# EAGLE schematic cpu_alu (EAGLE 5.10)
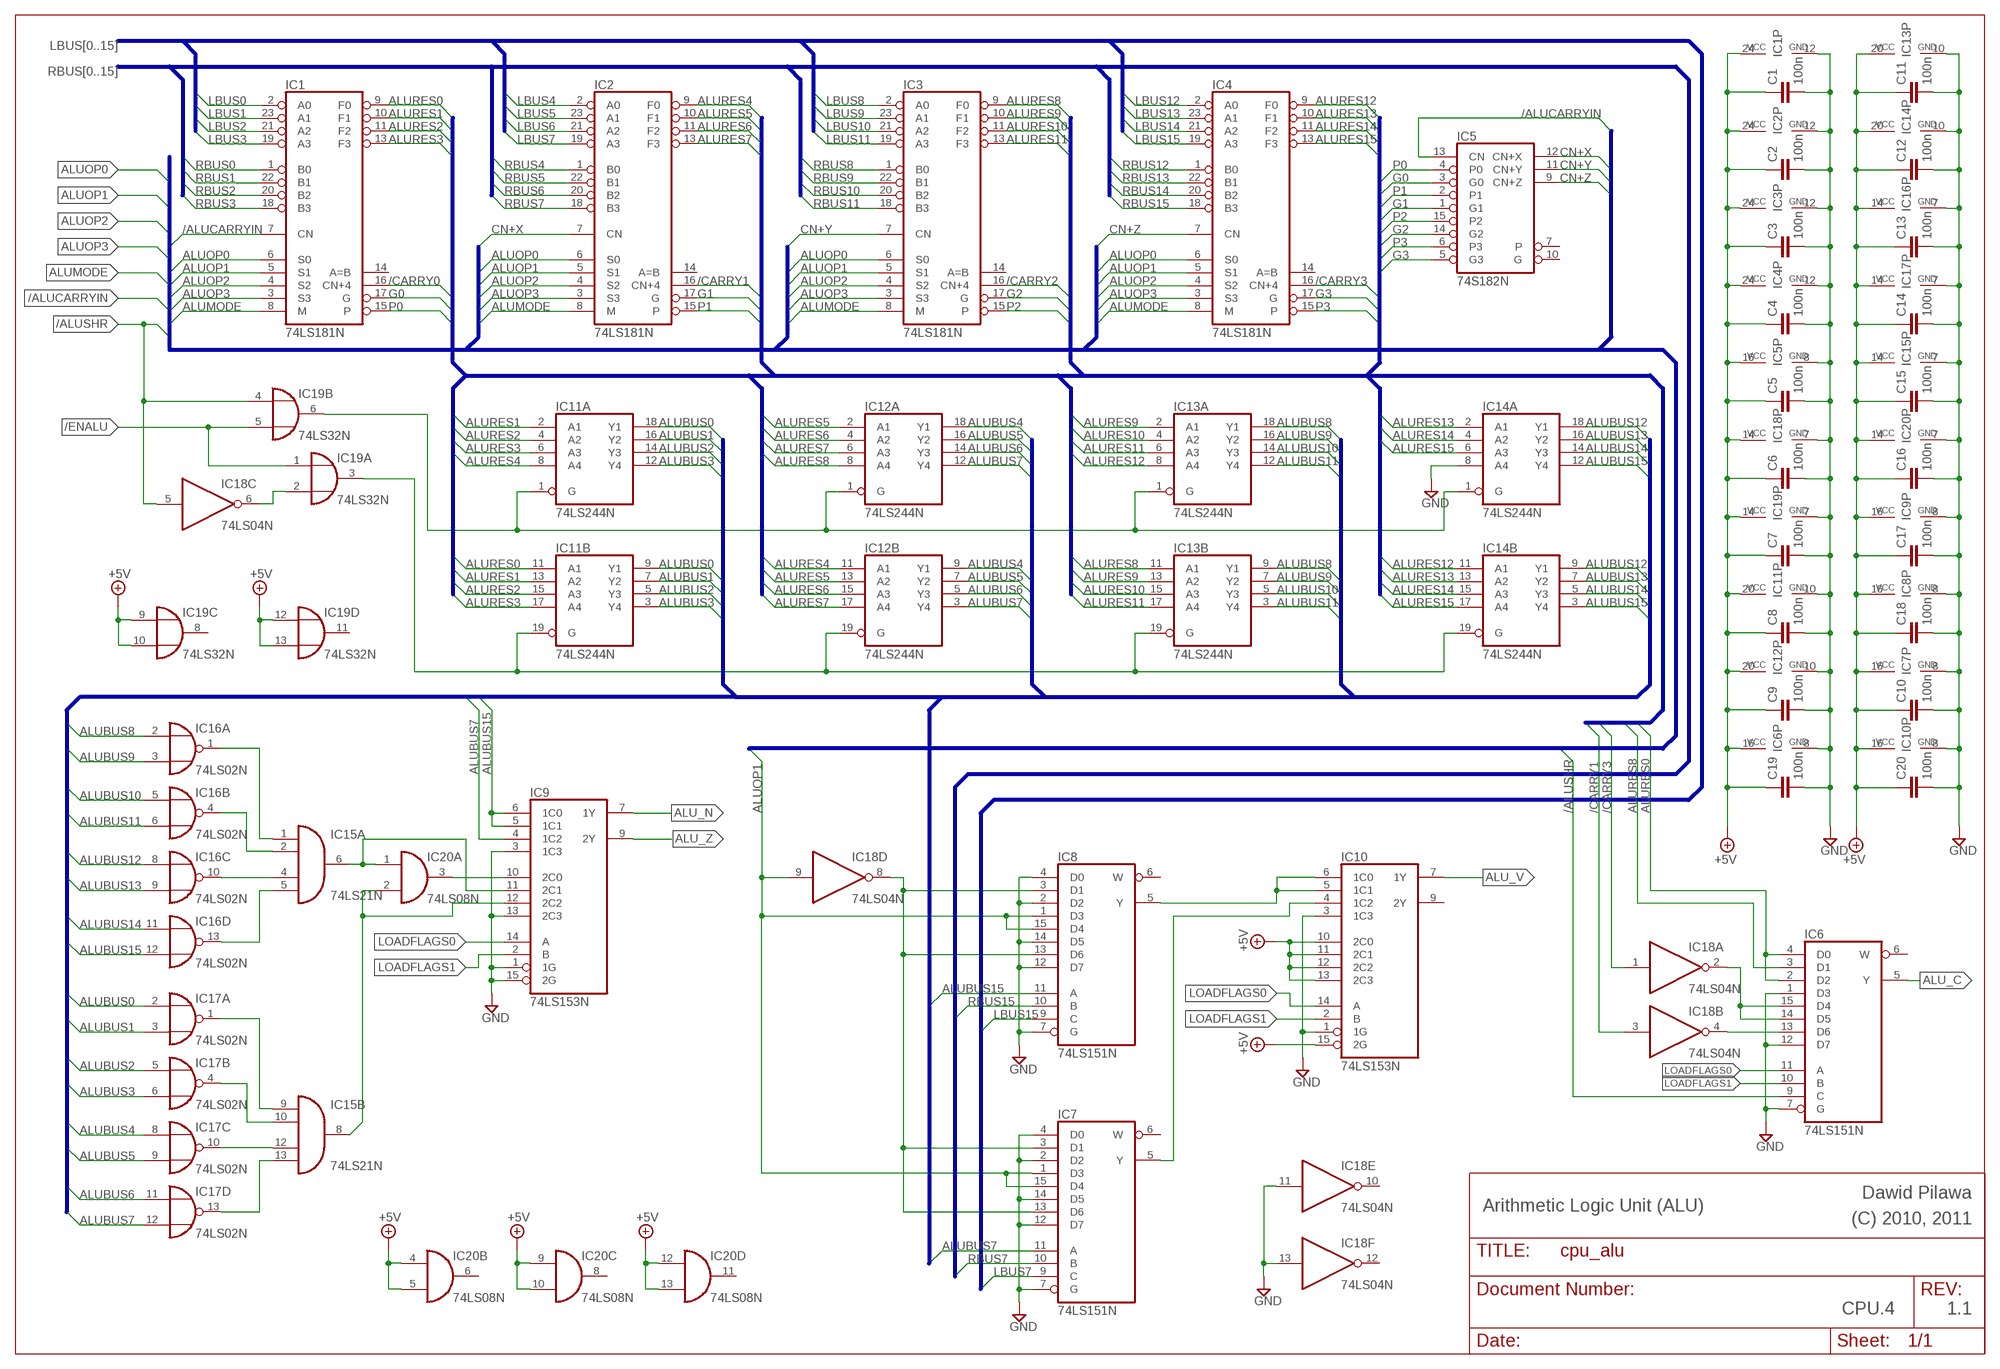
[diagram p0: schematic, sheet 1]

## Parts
C1  100n  C-EU050-024X044  [C050-024X044]
C2  100n  C-EU050-024X044  [C050-024X044]
C3  100n  C-EU050-024X044  [C050-024X044]
C4  100n  C-EU050-024X044  [C050-024X044]
C5  100n  C-EU050-024X044  [C050-024X044]
C6  100n  C-EU050-024X044  [C050-024X044]
C7  100n  C-EU050-024X044  [C050-024X044]
C8  100n  C-EU050-024X044  [C050-024X044]
C9  100n  C-EU050-024X044  [C050-024X044]
C10  100n  C-EU050-024X044  [C050-024X044]
C11  100n  C-EU050-024X044  [C050-024X044]
C12  100n  C-EU050-024X044  [C050-024X044]
C13  100n  C-EU050-024X044  [C050-024X044]
C14  100n  C-EU050-024X044  [C050-024X044]
C15  100n  C-EU050-024X044  [C050-024X044]
C16  100n  C-EU050-024X044  [C050-024X044]
C17  100n  C-EU050-024X044  [C050-024X044]
C18  100n  C-EU050-024X044  [C050-024X044]
C19  100n  C-EU050-024X044  [C050-024X044]
C20  100n  C-EU050-024X044  [C050-024X044]
IC1  74LS181N  [DIL24-6]
IC2  74LS181N  [DIL24-6]
IC3  74LS181N  [DIL24-6]
IC4  74LS181N  [DIL24-6]
IC5  74S182N  [DIL16]
IC6  74LS151N  [DIL16]
IC7  74LS151N  [DIL16]
IC8  74LS151N  [DIL16]
IC9  74LS153N  [DIL16]
IC10  74LS153N  [DIL16]
IC11  74LS244N  [DIL20]
IC12  74LS244N  [DIL20]
IC13  74LS244N  [DIL20]
IC14  74LS244N  [DIL20]
IC15  74LS21N  [DIL14]
IC16  74LS02N  [DIL14]
IC17  74LS02N  [DIL14]
IC18  74LS04N  [DIL14]
IC19  74LS32N  [DIL14]
IC20  74LS08N  [DIL14]

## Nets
+5V: C1.1 C2.1 C3.1 C4.1 C5.1 C6.1 C7.1 C8.1 C9.1 C10.1 C11.1 C12.1 C13.1 C14.1 C15.1 C16.1 C17.1 C18.1 C19.1 C20.1 IC1.24(VCC) IC2.24(VCC) IC3.24(VCC) IC4.24(VCC) IC5.16(VCC) IC6.16(VCC) IC7.16(VCC) IC8.16(VCC) IC9.16(VCC) IC10.10(2C0) IC10.11(2C1) IC10.12(2C2) IC10.13(2C3) IC10.15(2G) IC10.16(VCC) IC11.20(P:VCC) IC12.20(P:VCC) IC13.20(P:VCC) IC14.20(P:VCC) IC15.14(P:VCC) IC16.14(P:VCC) IC17.14(P:VCC) IC18.14(P:VCC) IC19.9(C:I0) IC19.10(C:I1) IC19.12(D:I0) IC19.13(D:I1) IC19.14(P:VCC) IC20.4(B:I0) IC20.5(B:I1) IC20.9(C:I0) IC20.10(C:I1) IC20.12(D:I0) IC20.13(D:I1) IC20.14(P:VCC)
/ALUCARRYIN: IC1.7(CN) IC5.13(CN)
/ALUSHR: IC6.9(C) IC18.5(C:I) IC19.4(B:I0)
/CARRY0: IC1.16(CN+4)
/CARRY1: IC2.16(CN+4) IC18.3(B:I)
/CARRY2: IC3.16(CN+4)
/CARRY3: IC4.16(CN+4) IC18.1(A:I)
/ENALU: IC19.1(A:I0) IC19.5(B:I1)
ALU_C: IC6.5(Y)
ALU_N: IC9.7(1Y)
ALU_V: IC10.7(1Y)
ALU_Z: IC9.9(2Y)
ALUBUS0: IC11.9(B:Y1) IC11.18(A:Y1) IC17.2(A:I0)
ALUBUS1: IC11.7(B:Y2) IC11.16(A:Y2) IC17.3(A:I1)
ALUBUS2: IC11.5(B:Y3) IC11.14(A:Y3) IC17.5(B:I0)
ALUBUS3: IC11.3(B:Y4) IC11.12(A:Y4) IC17.6(B:I1)
ALUBUS4: IC12.9(B:Y1) IC12.18(A:Y1) IC17.8(C:I0)
ALUBUS5: IC12.7(B:Y2) IC12.16(A:Y2) IC17.9(C:I1)
ALUBUS6: IC12.5(B:Y3) IC12.14(A:Y3) IC17.11(D:I0)
ALUBUS7: IC7.11(A) IC9.4(1C2) IC12.3(B:Y4) IC12.12(A:Y4) IC17.12(D:I1)
ALUBUS8: IC13.9(B:Y1) IC13.18(A:Y1) IC16.2(A:I0)
ALUBUS9: IC13.7(B:Y2) IC13.16(A:Y2) IC16.3(A:I1)
ALUBUS10: IC13.5(B:Y3) IC13.14(A:Y3) IC16.5(B:I0)
ALUBUS11: IC13.3(B:Y4) IC13.12(A:Y4) IC16.6(B:I1)
ALUBUS12: IC14.9(B:Y1) IC14.18(A:Y1) IC16.8(C:I0)
ALUBUS13: IC14.7(B:Y2) IC14.16(A:Y2) IC16.9(C:I1)
ALUBUS14: IC14.5(B:Y3) IC14.14(A:Y3) IC16.11(D:I0)
ALUBUS15: IC8.11(A) IC9.5(1C1) IC9.6(1C0) IC14.3(B:Y4) IC14.12(A:Y4) IC16.12(D:I1)
ALUMODE: IC1.8(M) IC2.8(M) IC3.8(M) IC4.8(M)
ALUOP0: IC1.6(S0) IC2.6(S0) IC3.6(S0) IC4.6(S0)
ALUOP1: IC1.5(S1) IC2.5(S1) IC3.5(S1) IC4.5(S1) IC7.1(D3) IC7.15(D4) IC8.1(D3) IC8.15(D4) IC18.9(D:I)
ALUOP2: IC1.4(S2) IC2.4(S2) IC3.4(S2) IC4.4(S2)
ALUOP3: IC1.3(S3) IC2.3(S3) IC3.3(S3) IC4.3(S3)
ALURES0: IC1.9(F0) IC6.2(D2) IC6.4(D0) IC11.11(B:A1)
ALURES1: IC1.10(F1) IC11.2(A:A1) IC11.13(B:A2)
ALURES2: IC1.11(F2) IC11.4(A:A2) IC11.15(B:A3)
ALURES3: IC1.13(F3) IC11.6(A:A3) IC11.17(B:A4)
ALURES4: IC2.9(F0) IC11.8(A:A4) IC12.11(B:A1)
ALURES5: IC2.10(F1) IC12.2(A:A1) IC12.13(B:A2)
ALURES6: IC2.11(F2) IC12.4(A:A2) IC12.15(B:A3)
ALURES7: IC2.13(F3) IC12.6(A:A3) IC12.17(B:A4)
ALURES8: IC3.9(F0) IC6.3(D1) IC12.8(A:A4) IC13.11(B:A1)
ALURES9: IC3.10(F1) IC13.2(A:A1) IC13.13(B:A2)
ALURES10: IC3.11(F2) IC13.4(A:A2) IC13.15(B:A3)
ALURES11: IC3.13(F3) IC13.6(A:A3) IC13.17(B:A4)
ALURES12: IC4.9(F0) IC13.8(A:A4) IC14.11(B:A1)
ALURES13: IC4.10(F1) IC14.2(A:A1) IC14.13(B:A2)
ALURES14: IC4.11(F2) IC14.4(A:A2) IC14.15(B:A3)
ALURES15: IC4.13(F3) IC14.6(A:A3) IC14.17(B:A4)
CN+X: IC2.7(CN) IC5.12(CN+X)
CN+Y: IC3.7(CN) IC5.11(CN+Y)
CN+Z: IC4.7(CN) IC5.9(CN+Z)
G0: IC1.17(G) IC5.3(G0)
G1: IC2.17(G) IC5.1(G1)
G2: IC3.17(G) IC5.14(G2)
G3: IC4.17(G) IC5.5(G3)
GND: C1.2 C2.2 C3.2 C4.2 C5.2 C6.2 C7.2 C8.2 C9.2 C10.2 C11.2 C12.2 C13.2 C14.2 C15.2 C16.2 C17.2 C18.2 C19.2 C20.2 IC1.12(GND) IC2.12(GND) IC3.12(GND) IC4.12(GND) IC5.8(GND) IC6.1(D3) IC6.7(G) IC6.8(GND) IC6.12(D7) IC7.2(D2) IC7.4(D0) IC7.7(G) IC7.8(GND) IC7.12(D7) IC7.14(D5) IC8.2(D2) IC8.4(D0) IC8.7(G) IC8.8(GND) IC8.12(D7) IC8.14(D5) IC9.1(1G) IC9.3(1C3) IC9.8(GND) IC9.13(2C3) IC9.15(2G) IC10.1(1G) IC10.3(1C3) IC10.8(GND) IC11.10(P:GND) IC12.10(P:GND) IC13.10(P:GND) IC14.8(A:A4) IC14.10(P:GND) IC15.7(P:GND) IC16.7(P:GND) IC17.7(P:GND) IC18.7(P:GND) IC18.11(E:I) IC18.13(F:I) IC19.7(P:GND) IC20.7(P:GND)
LBUS0: IC1.2(A0)
LBUS1: IC1.23(A1)
LBUS2: IC1.21(A2)
LBUS3: IC1.19(A3)
LBUS4: IC2.2(A0)
LBUS5: IC2.23(A1)
LBUS6: IC2.21(A2)
LBUS7: IC2.19(A3) IC7.9(C)
LBUS8: IC3.2(A0)
LBUS9: IC3.23(A1)
LBUS10: IC3.21(A2)
LBUS11: IC3.19(A3)
LBUS12: IC4.2(A0)
LBUS13: IC4.23(A1)
LBUS14: IC4.21(A2)
LBUS15: IC4.19(A3) IC8.9(C)
LOADFLAGS0: IC6.11(A) IC9.14(A) IC10.14(A)
LOADFLAGS1: IC6.10(B) IC9.2(B) IC10.2(B)
N$1: IC11.1(A:G) IC12.1(A:G) IC13.1(A:G) IC14.1(A:G) IC19.6(B:O)
N$2: IC6.13(D6) IC18.4(B:O)
N$3: IC6.14(D5) IC6.15(D4) IC18.2(A:O)
N$4: IC18.6(C:O) IC19.2(A:I1)
N$5: IC11.19(B:G) IC12.19(B:G) IC13.19(B:G) IC14.19(B:G) IC19.3(A:O)
N$6: IC15.1(A:I0) IC16.1(A:O)
N$7: IC15.2(A:I1) IC16.4(B:O)
N$8: IC15.4(A:I2) IC16.10(C:O)
N$9: IC15.5(A:I3) IC16.13(D:O)
N$10: IC15.9(B:I0) IC17.1(A:O)
N$11: IC15.10(B:I1) IC17.4(B:O)
N$12: IC15.12(B:I2) IC17.10(C:O)
N$13: IC15.13(B:I3) IC17.13(D:O)
N$14: IC9.11(2C1) IC15.6(A:O) IC20.1(A:I0)
N$15: IC9.12(2C2) IC15.8(B:O) IC20.2(A:I1)
N$16: IC9.10(2C0) IC20.3(A:O)
N$17: IC8.5(Y) IC10.5(1C1) IC10.6(1C0)
N$19: IC7.5(Y) IC10.4(1C2)
N$21: IC7.3(D1) IC7.13(D6) IC8.3(D1) IC8.13(D6) IC18.8(D:O)
P0: IC1.15(P) IC5.4(P0)
P1: IC2.15(P) IC5.2(P1)
P2: IC3.15(P) IC5.15(P2)
P3: IC4.15(P) IC5.6(P3)
RBUS0: IC1.1(B0)
RBUS1: IC1.22(B1)
RBUS2: IC1.20(B2)
RBUS3: IC1.18(B3)
RBUS4: IC2.1(B0)
RBUS5: IC2.22(B1)
RBUS6: IC2.20(B2)
RBUS7: IC2.18(B3) IC7.10(B)
RBUS8: IC3.1(B0)
RBUS9: IC3.22(B1)
RBUS10: IC3.20(B2)
RBUS11: IC3.18(B3)
RBUS12: IC4.1(B0)
RBUS13: IC4.22(B1)
RBUS14: IC4.20(B2)
RBUS15: IC4.18(B3) IC8.10(B)
Unconnected: IC1.14(A=B) IC2.14(A=B) IC3.14(A=B) IC4.14(A=B) IC5.7(P) IC5.10(G) IC6.6(W) IC7.6(W) IC8.6(W) IC10.9(2Y) IC18.10(E:O) IC18.12(F:O) IC19.8(C:O) IC19.11(D:O) IC20.6(B:O) IC20.8(C:O) IC20.11(D:O)

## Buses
RBUS[0..15]
LBUS[0..15]
ALUOP[0..3],ALUMODE,/ALUSHR,/ALUCARRYIN,CN+X,CN+Y,CN+Z
ALURES[0..15],/CARRY[0..3],P[0..3],G[0..3]
ALUBUS[0..15]

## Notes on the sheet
- Dawid Pilawa
- Arithmetic Logic Unit (ALU) | (C) 2010, 2011
- CPU.4 | 1.1

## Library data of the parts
C1-C20 = rcl:C-EU: CAPACITOR, European symbol
IC1-IC4 = 74xx-eu:74*181: ARITHMETIC LOGIC UNIT function generator
IC5 = 74xx-eu:74*182: LOOK AHEAD CARRY GENERATOR
IC6-IC8 = 74xx-eu:74*151: Data SELECTOR/MULTIPLEXER
IC9 IC10 = 74xx-eu:74*153: Dual 4-line to 1-line data SELECTOR/MULTIPLEXER
IC11-IC14 = 74xx-eu:74*244: Octal BUFFER and LINE DRIVER, 3-state
IC15 = 74xx-eu:74*21: Dual 4-input AND gate
IC16 IC17 = 74xx-eu:74*02: Quad 2-input NOR gate
IC18 = 74xx-eu:74*04: Hex INVERTER
IC19 = 74xx-eu:74*32: Quad 2-input OR gate
IC20 = 74xx-eu:74*08: Quad 2-input AND gate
